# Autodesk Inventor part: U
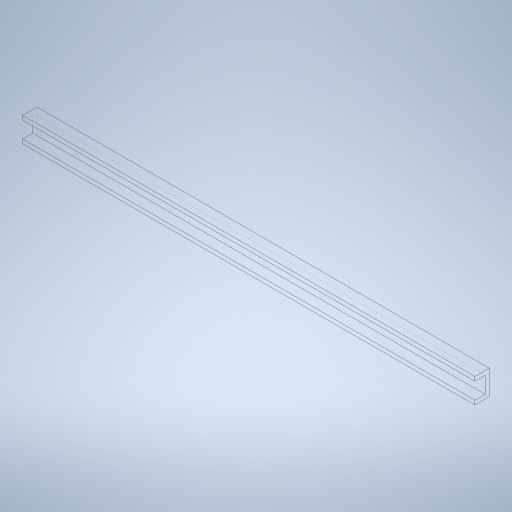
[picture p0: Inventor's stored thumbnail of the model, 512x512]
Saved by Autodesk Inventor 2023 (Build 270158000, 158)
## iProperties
Created: 2023-11
Part Number: U
Material: Generic
Document SubType Name: Modeling
Designer: tornqvih
Density: 1 g/cm^3
Appearance: Default
Author: tornqvih
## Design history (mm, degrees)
sketch "Sketch1"
  geometry: L1 (6, 2.5)-(6, -4.5); L2 (6, -4.5)-(-6, -4.5); L3 (-6, -4.5)-(-6, 2.5); L4 (-6, 2.5)-(-4, 2.5); L5 (-4, 2.5)-(-4, -2.5); L6 (-4, -2.5)-(4, -2.5); L7 (4, -2.5)-(4, 2.5); L8 (4, 2.5)-(6, 2.5); L9 (0, -5.9)-(0, 3.9) reference; L10 (-8.4, 0)-(8.4, 0) reference; 1 further point
  constraints: 16 end point, 5 symmetric about line, 2 vertical, 1 horizontal alignment, 1 point on line
  dimensions: "d0" = 5 distance of L6.end L7.end; "d1" = 2 distance between parallel lines of L1 L7; "d2" = 2 distance between parallel lines of L2 L6; "d3" = 8 distance of L5.end L6.end
extrude "Extrusion1" new body sketch "Sketch1" distance "d4" = 220; taper "d5" = 0 deg
body "Solid1"
